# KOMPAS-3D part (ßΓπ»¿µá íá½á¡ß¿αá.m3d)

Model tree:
1. Эскиз:1
2. Операция выдавливания:1
     Расстояние 1 = 16
3. Эскиз:3
4. Операция выдавливания:2
     Расстояние 1 = 16; Расстояние 2 = 4
5. Эскиз:12
6. Операция выдавливания:3
     Расстояние 1 = 9; Расстояние 2 = 9
7. Эскиз:14
8. Операция выдавливания:4
     Расстояние 1 = 9; Расстояние 2 = 16
9. Эскиз:15
10. Вырезать элемент выдавливания:10
     Расстояние 1 = 2
11. Эскиз:16
12. Вырезать элемент выдавливания:11
     Расстояние 1 = 16
13. Скругление:8
     Радиус = 0.5
14. Скругление:9
     Радиус = 0.5
15. Скругление:10
     Радиус = 0.2
16. Скругление:11
     Радиус = 0.5
17. Эскиз:18
18. Вырезать элемент выдавливания:13
     Расстояние 1 = 4
19. Эскиз:19
20. Вырезать элемент выдавливания:14
     Расстояние 1 = 2

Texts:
  Сплав АЛ8  ГОСТ 1583-93
  stalker61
